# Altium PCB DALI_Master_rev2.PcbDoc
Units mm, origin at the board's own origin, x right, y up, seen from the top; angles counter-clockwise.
Board outline 90 x 50 mm, 2 copper layers (Top Layer, Bottom Layer); 97 components, 67 nets, 341 pads, 118 vias.
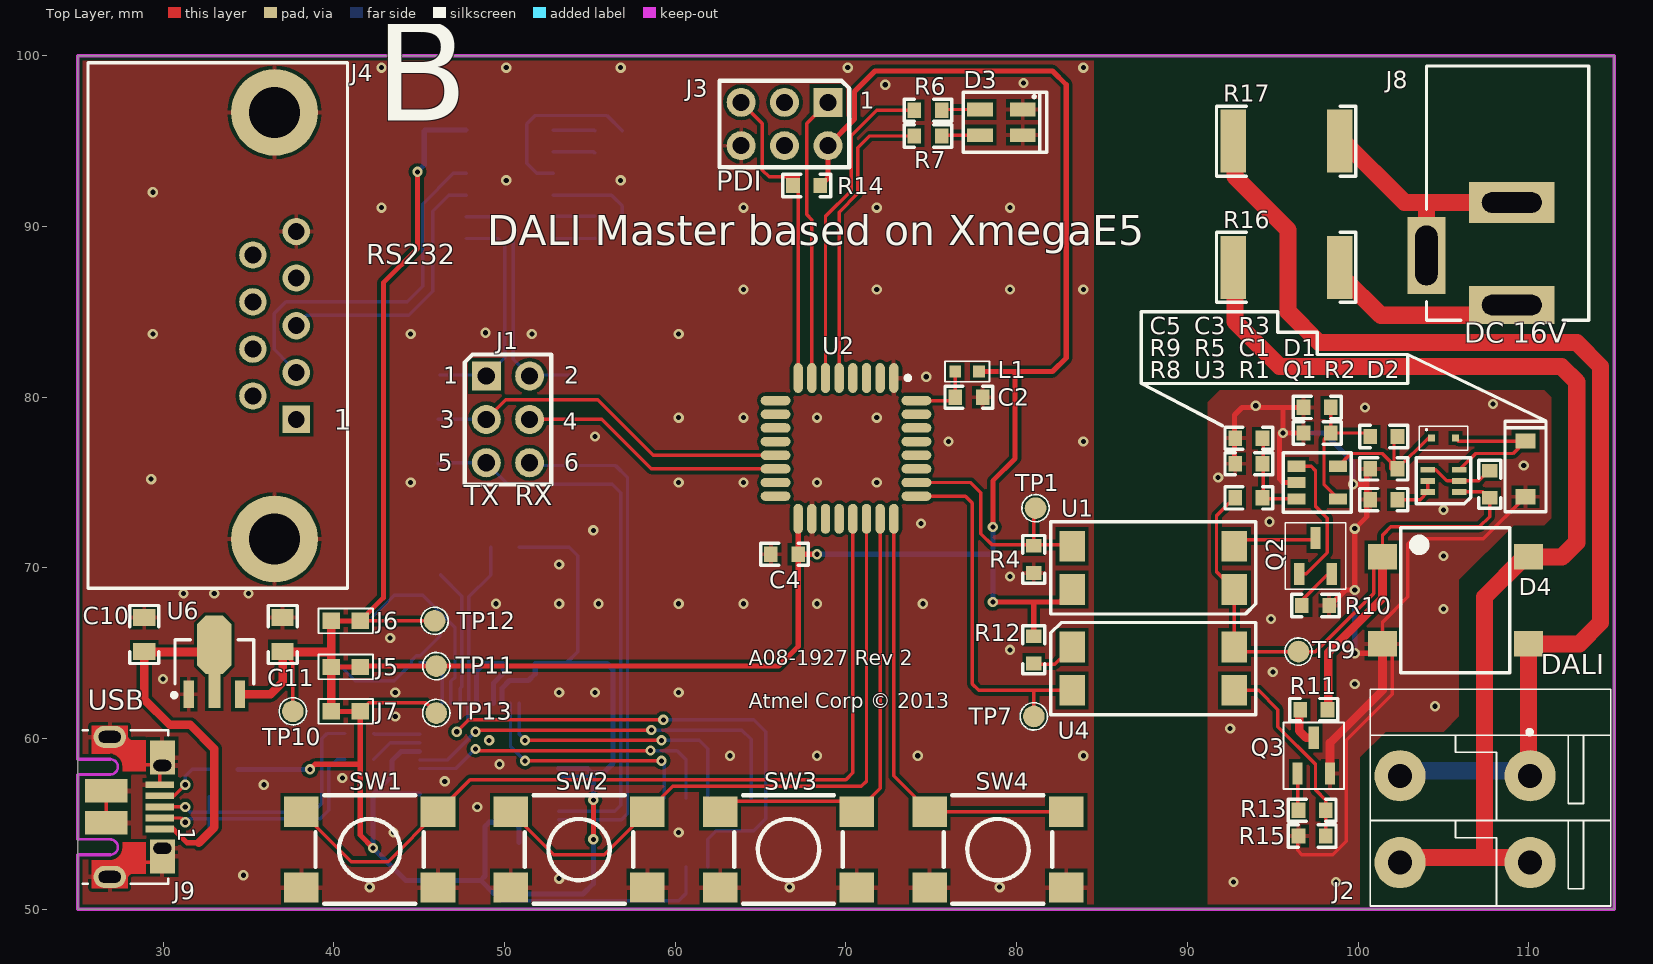
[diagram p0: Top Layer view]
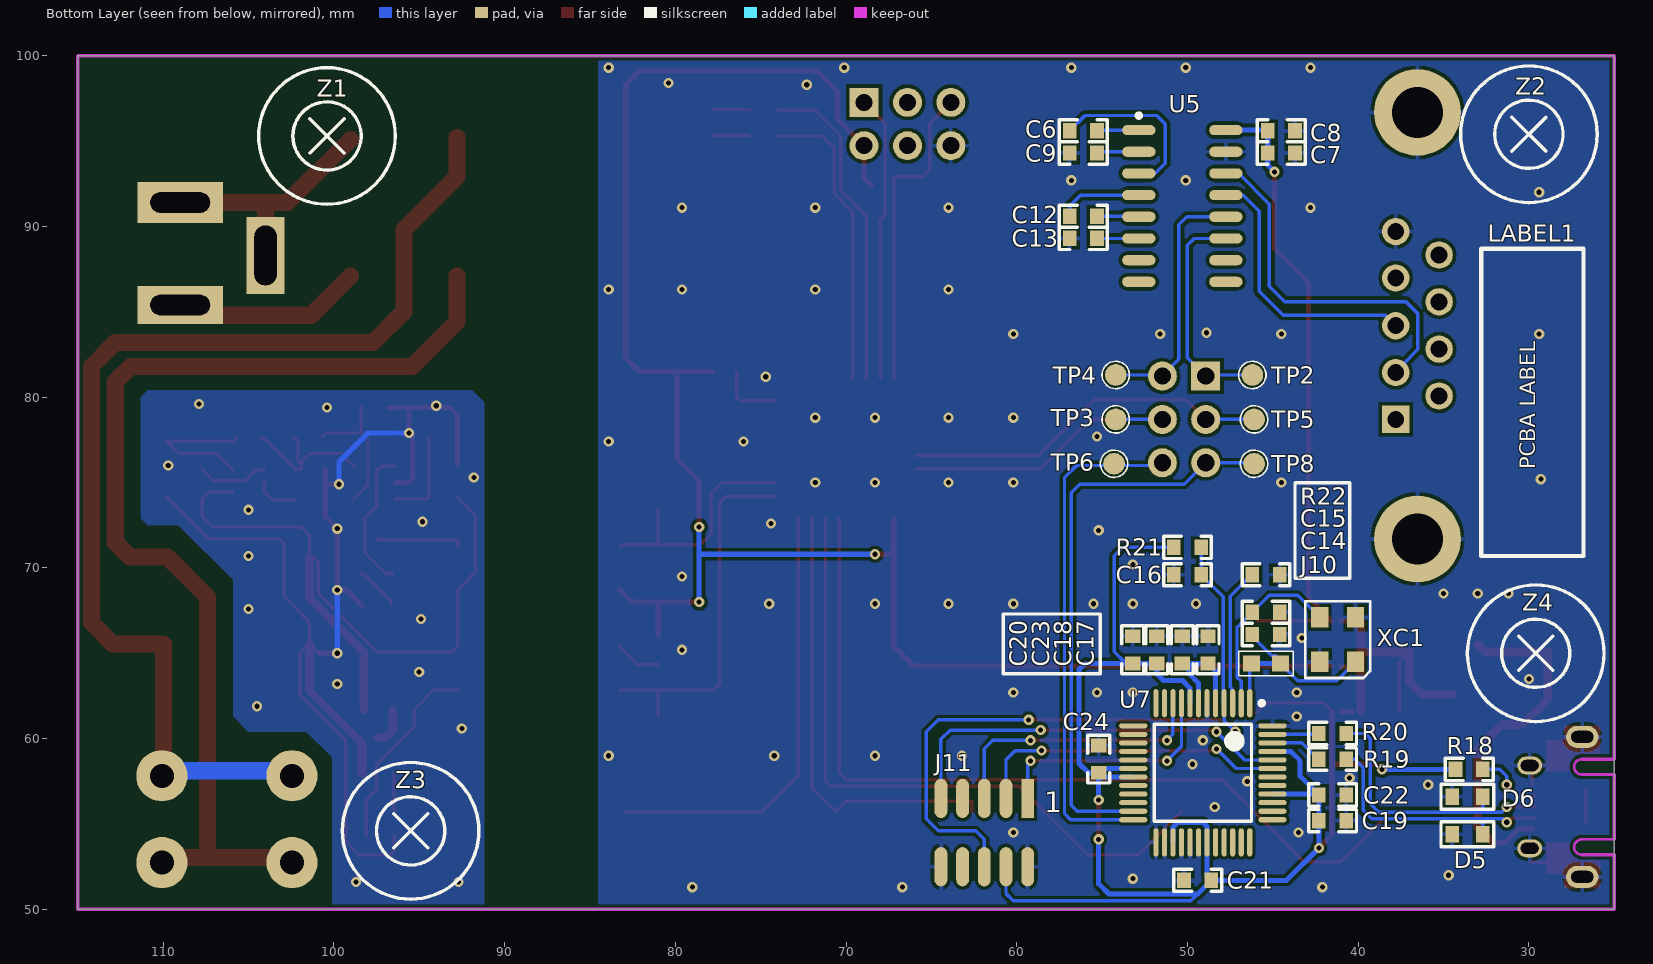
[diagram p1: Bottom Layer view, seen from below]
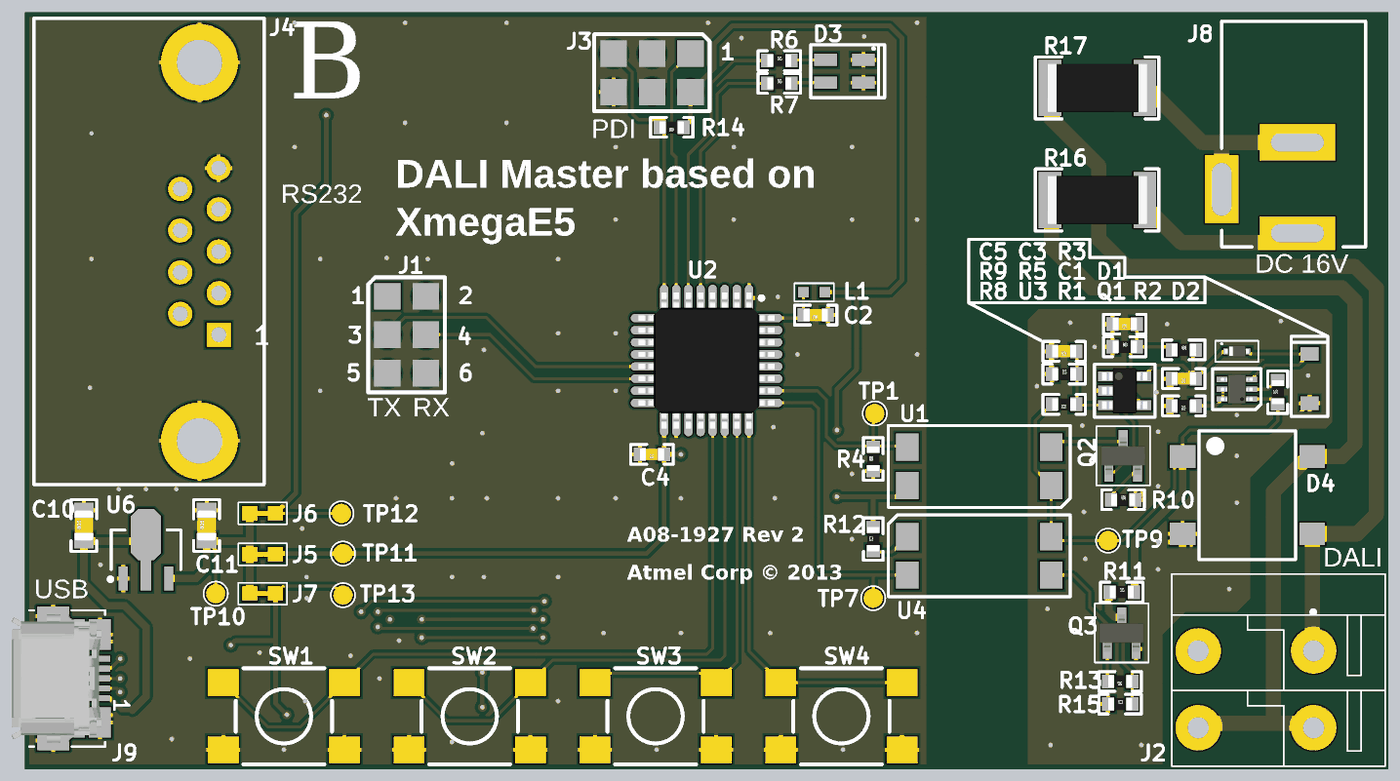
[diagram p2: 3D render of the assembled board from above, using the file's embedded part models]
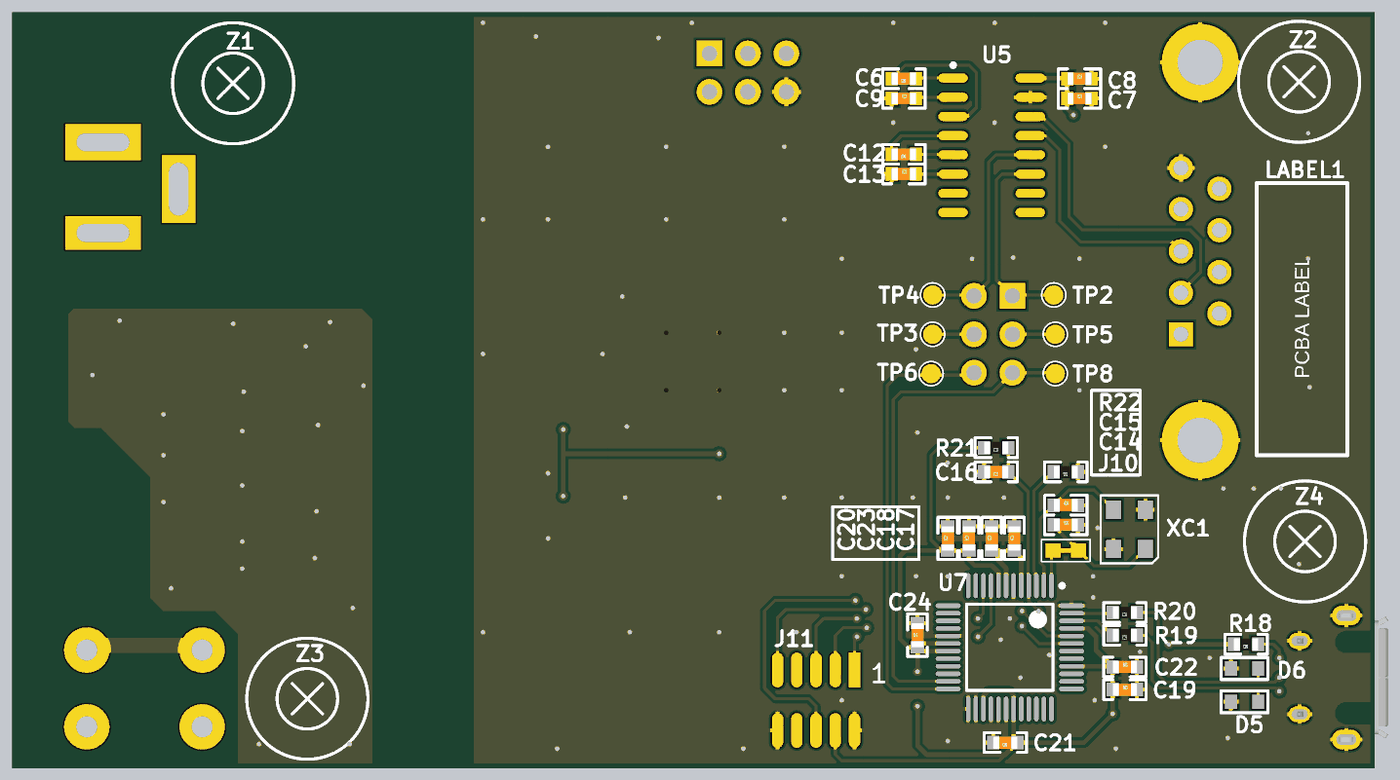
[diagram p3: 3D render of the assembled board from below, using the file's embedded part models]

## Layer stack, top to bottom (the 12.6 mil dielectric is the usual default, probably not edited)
Top Layer: signal copper 0.0356
Dielectric: dielectric 0.32, FR-4, Dk 4.8
Bottom Layer: signal copper 0.0356

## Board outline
25,50 25,100 115,100 115,50

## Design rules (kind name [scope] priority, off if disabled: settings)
Clearance [All] p1: gap=0.2
HoleSize [All] p1: absolutevalues=TRUE maxlimit=3.5 minlimit=0.025 maxpercent=80.000 minpercent=20.000
MinimumSolderMaskSliver [All] p1: minsoldermaskwidth=0.1
PolygonConnect [(InPadClass('All Pads'))] p1: connectstyle=Relief reliefconductorwidth=0.254 reliefentries=4 polygonreliefangle="90 Angle"
PolygonConnect PolygonConnect_1 [All] p2: connectstyle=Direct reliefconductorwidth=0.254 reliefentries=4 polygonreliefangle="90 Angle"
RoutingVias [All] p1: holewidth=0.3 width=0.6 viastyle="Through Hole" minholewidth=0.3 minwidth=0.6 maxholewidth=0.7 maxwidth=1
SilkscreenOverComponentPads [All] p1: minsilkscreentomaskgap=0.254
SolderMaskExpansion [All] p1: expansion=0.102
Width [All] p1: maxlimit=2 minlimit=0.2 preferedwidth=0.2
25 further rules are at their usual default settings.

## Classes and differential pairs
component class DALI_Master_Main_rev2: C1 C2 C3 C4 C5 D1 D2 D3 D4 J1 J2 J3 L1 LABEL1 Q1 Q2 Q3 R1 R2 R3 R4 R5 R6 R7 R8 R9 R10 R11 R12 R13 R14 R15 SW1 SW2 SW3 SW4 TP1 TP2 TP3 TP4 TP5 TP6 TP7 TP8 TP9 U1 U2 U3 U4 Z1 Z2 Z3 Z4
component class DALI_Master_Others_rev2: C6 C7 C8 C9 C10 C11 C12 C13 C14 C15 C16 C17 C18 C19 C20 C21 C22 C23 C24 D5 D6 J4 J5 J6 J7 J8 J9 J10 J11 R16 R17 R18 R19 R20 R21 R22 TP10 TP11 TP12 TP13 U5 U6 U7 U? XC1

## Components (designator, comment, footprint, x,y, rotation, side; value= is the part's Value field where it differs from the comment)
C1 "1735527 @ element14" AP1-00096#1 101.5,75.8 r180 top
C2 "1828890 @ element14" AP1-00096#1 77.2,80 r180 top
C3 "8819955 @ element14" AP1-00096#1 97.6,79.4 r180 top
C4 "1828890 @ element14" AP1-00096#1 66.4,70.8 r180 top
C5 "8819866 @ element14" AP1-00096#1 93.6,77.6 r180 top
C6 "1828890 @ element14" AP1-00096#2 56.1,95.6 r0 bottom
C7 "1735527 @ element14" AP1-00096#2 44.5,94.3 r180 bottom
C8 "1828890 @ element14" AP1-00096#2 44.5,95.6 r180 bottom
C9 "1828890 @ element14" AP1-00096#2 56.1,94.3 r180 bottom
C10 "1889282 @ element14" AP1-00097 28.9,66.1 r90 top
C11 "1889282 @ element14" AP1-00097 37,66.1 r90 top
C12 "1828890 @ element14" AP1-00096#2 56.1,90.6 r0 bottom
C13 "1828890 @ element14" AP1-00096#2 56.1,89.3 r180 bottom
C14 "1828907 @ element14" AP1-00096#1 45.4,66.1 r180 bottom
C15 "1828907 @ element14" AP1-00096#1 45.4,67.4 r180 bottom
C16 "1828890 @ element14" AP1-00096#1 50,69.6 r0 bottom
C17 "1735527 @ element14" AP1-00096#1 48.8,65.2 r90 bottom
C18 "1828890 @ element14" AP1-00096#1 50.3,65.2 r90 bottom
C19 "1735527 @ element14" AP1-00096#1 41.5,55.2 r180 bottom
C20 "1735527 @ element14" AP1-00096#1 53.2,65.2 r90 bottom
C21 "1828890 @ element14" AP1-00096#1 49.4,51.7 r0 bottom
C22 "1828890 @ element14" AP1-00096#1 41.5,56.7 r180 bottom
C23 "1828890 @ element14" AP1-00096#1 51.8,65.2 r90 bottom
C24 "1828890 @ element14" AP1-00096#1 55.2,58.8 r90 bottom
D1 "Farnell# 1615809" AP4-00036 105,77.6 r0 top
D2 "ZENER_SMD_12" AP4-00012 109.8,75.8 r90 top
D3 "LED2" AP4-00030 79.1,96.1 r0 top
D4 "DIODEBRIDGE" AP4-00009 105.7,68.1 r0 top
D5 "TransGuard" AP4-00024 33.6,54.4 r0 bottom
D6 "TransGuard" AP4-00024 33.6,56.6 r0 bottom
J1 "HEADER 2x3" AP8-00182 50.2,78.7 r270 top
J2 "Cable_connector_2Pin" AP8-00788 100.7,50.2 r270 top
J3 "HEADER 2x3" AP8-00182 66.4,96 r180 top
J4 "DSUB9" AP8-00516 37.8,78.7 r90 top
J5 "SMD-STRAP_CLOSED" AP9-00044#1 40.7,64.2 r180 top net-tie
J6 "SMD-STRAP_CLOSED" AP9-00044#2 40.7,66.9 r180 top net-tie
J7 "SMD-STRAP_CLOSED" AP9-00044#2 40.7,61.6 r180 top net-tie
J8 "Farnel #224959" AP8-00017 109,99 r270 top
J9 "USB_Micro" AP8-00610 29.8,56 r270 top
J10 "SMD-STRAP_CLOSED" AP9-00044#1 45.4,64.4 r180 bottom net-tie
J11 "2x5 Header" AP8-00514 61.9,54.5 r0 bottom
L1 "INDUCTOR" AP3-00005 77.1,81.5 r180 top
LABEL1 "Label PCBA" AP8-00317 26.8,70.7 r90 bottom
Q1 "PNP DUAL" AP5-00001 105,75.1 r180 top
Q2 "1081232 @ element14" AP5-00002 97.5,70.7 r90 top
Q3 "NPN BEC" AP5-00002 97.4,59 r90 top
R1 "9238743 @ element14" AP2-00066 101.5,74 r180 top
R2 "1799353 @ element14" AP2-00066 107.7,74.9 r90 top
R3 "9238840 @ element14" AP2-00066 101.5,77.7 r0 top
R4 "1799353 @ element14" AP2-00066 81,70.5 r90 top
R5 "9238840 @ element14" AP2-00066 97.6,77.9 r0 top
R6 "1255619 @element14" AP2-00066 74.8,96.8 r0 top
R7 "9238425 @element14" AP2-00066 74.8,95.3 r0 top
R8 "9238840 @ element14" AP2-00066 93.6,74.1 r180 top
R9 "R2" AP2-00066 93.6,76.1 r0 top
R10 "9238506 @element14" AP2-00066 97.5,67.8 r0 top
R11 "9238123 @ element14" AP2-00066 97.4,61.7 r0 top
R12 "1799335 @ element14" AP2-00066 81,65.2 r90 top
R13 "9238379 @element14" AP2-00066 97.3,55.8 r180 top
R14 "9238603 @ element14" AP2-00066 67.7,92.4 r180 top
R15 "1255619 @element14" AP2-00066 97.3,54.3 r0 top
R16 "1283115 @ element14" AP2-00068 95.8,87.6 r180 top
R17 "1283115 @ element14" AP2-00068 95.8,95 r180 top
R18 "9238689 @ element14" AP2-00066 33.5,58.2 r0 bottom
R19 "9238310 @ element14" AP2-00066 41.5,58.8 r0 bottom
R20 "9238310 @ element14" AP2-00066 41.5,60.3 r0 bottom
R21 "9238603 @ element14" AP2-00066 50,71.2 r0 bottom
R22 "9238603 @ element14" AP2-00066 45.4,69.6 r0 bottom
SW1 "B3S-1000P also can be used as MPN.Packaging difference only" AP8-00481 42.1,53.5 r90 top
SW2 "B3S-1000P also can be used as MPN.Packaging difference only" AP8-00481 54.367,53.5 r90 top
SW3 "B3S-1000P also can be used as MPN.Packaging difference only" AP8-00481 66.633,53.5 r90 top
SW4 "B3S-1000P also can be used as MPN.Packaging difference only" AP8-00481 78.9,53.5 r90 top
TP1 "INPUT" AP8-00499 81.1,73.5 r0 top
TP2 "" AP8-00499 46.2,81.3 r270 bottom
TP3 "" AP8-00499 54.2,78.7 r270 bottom
TP4 "" AP8-00499 54.2,81.3 r270 bottom
TP5 "" AP8-00499 46.1,78.7 r270 bottom
TP6 "" AP8-00499 54.3,76.1 r270 bottom
TP7 "OUTPUT" AP8-00499 81,61.3 r90 top
TP8 "" AP8-00499 46.1,76.1 r270 bottom
TP9 "" AP8-00499 96.5,65.1 r90 top
TP10 "+3V3" AP8-00499 37.6,61.6 r90 top
TP11 "" AP8-00499 46,64.25 r90 top
TP12 "" AP8-00499 45.9,66.9 r90 top
TP13 "" AP8-00499 46,61.5 r90 top
U1 "IS357" AP6-00142 88,70 r0 top
U2 "ATxmega32E5_TQFP" AP6-00061 70,77 r270 top
U3 "TLV3491" AP6-00087 97.6,75 r0 top
U4 "IS357" AP6-00142 88,64.1 r180 top
U5 "MAX3232" AP6-00122 50.3,91.2 r180 bottom
U6 "HT7533-2" AP5-00036 33,64.5 r90 top
U7 "ATSAM4LC2A" AP6-00004 49.1,58 r270 bottom locked
XC1 "1836841 @ element14" AP7-00041 41.2,65.8 r90 bottom
Z1 "Datasheet & Drawing in AP8-00414" AP8-00414 100.4,95.3 r180 bottom
Z2 "Datasheet & Drawing in AP8-00414" AP8-00414 30,95.4 r180 bottom
Z3 "Datasheet & Drawing in AP8-00414" AP8-00414 95.5,54.6 r180 bottom
Z4 "Datasheet & Drawing in AP8-00414" AP8-00414 29.6,65 r180 bottom

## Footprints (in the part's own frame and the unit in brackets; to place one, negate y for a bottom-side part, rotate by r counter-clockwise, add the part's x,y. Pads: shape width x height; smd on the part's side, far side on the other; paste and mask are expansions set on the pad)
AP1-00096#1 [mm] "0603 SMD capacitor footprint used by SHAPPS"
  rect 0.8x0.9 smd: 1(-0.8,0) 2(0.8,0)
  silkscreen extent -1.4,-0.65 1.4,0.65, body extent -0.8,-0.4 0.8,0.4, height 0.3
AP1-00096#2 [mm] "0603 SMD capacitor footprint used by SHAPPS"
  rect 0.8x0.9 smd paste-10: 1(-0.8,0) 2(0.8,0)
  silkscreen extent -1.4,-0.65 1.4,0.65, body extent -0.8,-0.4 0.8,0.4, height 0.3
AP1-00097 [mm] "0805 SMD capacitor footprint used by SHAPPS"
  rect 1x1.3 smd: 1(-1,0) 2(1,0)
  silkscreen extent -1.7,-0.85 1.7,0.85, body extent -1,-0.63 1,0.63, height 0.78
AP2-00066 [mm] "0603 SMD resistor footprint used by SHAPPS"
  rect 0.8x0.9 smd: 1(-0.8,0) 2(0.8,0)
  silkscreen extent -1.4,-0.65 1.4,0.65, body extent -0.8,-0.4 0.8,0.4, height 0.3
AP2-00068 [mm] "2512 SMD Resistor"
  rect 1.5x3.7 smd: 1(-3.125,0) 2(3.125,0)
  silkscreen extent -4.05,-2.05 4.1,2.05, body extent -3.3,-1.6 3.3,1.6, height 0.84
AP3-00005 [mm]
  rect 0.7x0.7 smd: 1(-0.7,0) 2(0.7,0)
  silkscreen extent -1.3,-0.6 1.3,0.6, body extent -0.83,-0.41 0.82,0.41, height 0.8
AP4-00009 [mm] "SOIC, 4-Leads, Body 8.5x6.5mm (max), Pitch 1.27mm, IPC Medium Density"
  rect 1.7x1.5 smd: 1(-4.275,2.55) 2(-4.275,-2.55) 3(4.275,-2.55) 4(4.275,2.55)
  silkscreen extent -3.2,-4.25 3.17,4.25, body extent -3.25,-4.25 3.25,4.25, height 3.3
AP4-00012 [mm]
  rect 0.9x1.2 smd: 1(1.63,0) 2(-1.63,0)
  silkscreen extent -2.5,-1.2 2.8,1.2, body extent -1.69,-0.9 1.71,0.9, height 1.21
AP4-00024 [mm]
  rect 0.8x0.95 smd: 1(-0.9,0) 2(0.9,0)
  silkscreen extent -1.55,-0.73 1.55,0.73, body extent -0.85,-0.4 0.85,0.4, height 0.4
AP4-00030 [mm]
  rect 1.5x0.8 smd: 1(1.25,0.75) 2(-1.25,0.75) 3(1.25,-0.75) 4(-1.25,-0.75)
  silkscreen extent -2.22,-1.75 2.65,1.75, body extent -1.5,-1.25 1.5,1.25, height 1.31
AP4-00036 [mm] "Molded Diode, 2-Leads, Body 1,2x0,8mm, IPC Medium Density"
  rect 0.4x0.4 smd: 1(-0.7,0) 2(0.7,0)
  silkscreen extent -1.43,-0.7 1.43,0.7, body extent -0.8,-0.4 0.8,0.4, height 0.7
AP5-00001 [mm]
  rect 0.85x0.35 smd: 1(-0.925,0.65) 2(-0.925,0) 3(-0.925,-0.65) 4(0.925,-0.65) 5(0.925,0) 6(0.925,0.65)
  silkscreen extent -1.6,-1.35 1.6,1.35, body extent -1.05,-1 1.05,1, height 0.95
AP5-00002 [mm] "SOT-23 Package"
  rect 1.3x0.6 smd: 1(-1.05,0.95) 2(-1.05,-0.95) 3(1.05,0)
  silkscreen extent -1.95,-1.78 1.95,1.78, body extent -1.25,-1.46 1.23,1.46, height 1
AP5-00036 [mm] "SOT89, 3-Leads, Body 4.5x2.4 mm, Pitch 1.5mm, Lead Span 4.1mm, IPC Low Density"
  rect 1.6x0.6 smd: 1(-1.9,1.5) 3(-1.9,-1.5)
  rect 2x0.7 smd: 2(-1.7,0)
  oct 3.4x2 smd: 2(1,0)
  silkscreen extent -2.07,-2.3 1.3,2.47, body extent -1.3,-2.3 1.3,2.3, height 1.6
AP6-00004 [mm] "TSQFP, 48-Leads, Body 9,0x9,0mm (max), Pitch 0,50mm, IPC Medium Density"
  oval 1.65x0.3 smd mask+0.05: 1(-4.075,2.75) 2(-4.075,2.25) 3(-4.075,1.75) 4(-4.075,1.25) 5(-4.075,0.75) 6(-4.075,0.25) 7(-4.075,-0.25) 8(-4.075,-0.75) 9(-4.075,-1.25) 10(-4.075,-1.75) 11(-4.075,-2.25) 12(-4.075,-2.75) 25(4.075,-2.75) 26(4.075,-2.25) 27(4.075,-1.75) 28(4.075,-1.25) 29(4.075,-0.75) 30(4.075,-0.25) 31(4.075,0.25) 32(4.075,0.75) 33(4.075,1.25) 34(4.075,1.75) 35(4.075,2.25) 36(4.075,2.75)
  oval 0.3x1.65 smd mask+0.05: 13(-2.75,-4.075) 14(-2.25,-4.075) 15(-1.75,-4.075) 16(-1.25,-4.075) 17(-0.75,-4.075) 18(-0.25,-4.075) 19(0.25,-4.075) 20(0.75,-4.075) 21(1.25,-4.075) 22(1.75,-4.075) 23(2.25,-4.075) 24(2.75,-4.075) 37(2.75,4.075) 38(2.25,4.075) 39(1.75,4.075) 40(1.25,4.075) 41(0.75,4.075) 42(0.25,4.075) 43(-0.25,4.075) 44(-0.75,4.075) 45(-1.25,4.075) 46(-1.75,4.075) 47(-2.25,4.075) 48(-2.75,4.075)
  silkscreen extent -4.2,-2.85 2.85,3.57, body extent -3.5,-3.5 3.5,3.5, height 1.2
AP6-00061 [mm] "TQFP, 32-Leads, Body 9.3x9.3mm (max), Pitch 0.80mm, IPC Medium Density"
  oval 1.75x0.55 smd: 1(-4.125,2.8) 2(-4.125,2) 3(-4.125,1.2) 4(-4.125,0.4) 5(-4.125,-0.4) 6(-4.125,-1.2) 7(-4.125,-2) 8(-4.125,-2.8) 17(4.125,-2.8) 18(4.125,-2) 19(4.125,-1.2) 20(4.125,-0.4) 21(4.125,0.4) 22(4.125,1.2) 23(4.125,2) 24(4.125,2.8)
  oval 0.55x1.75 smd: 9(-2.8,-4.125) 10(-2,-4.125) 11(-1.2,-4.125) 12(-0.4,-4.125) 13(0.4,-4.125) 14(1.2,-4.125) 15(2,-4.125) 16(2.8,-4.125) 25(2.8,4.125) 26(2,4.125) 27(1.2,4.125) 28(0.4,4.125) 29(-0.4,4.125) 30(-1.2,4.125) 31(-2,4.125) 32(-2.8,4.125)
  silkscreen extent -4.25,3.5 -4,3.75, body extent -4.5,-4.5 4.5,4.5, height 1.44
AP6-00087 [mm]
  rect 1.05x0.65 smd: 1(-1.225,0.953) 2(-1.225,0) 3(-1.225,-0.953) 4(1.225,-0.953) 5(1.225,0.953)
  silkscreen extent -2,-1.75 2,1.75, body extent -1.5,-1.5 1.5,1.5, height 1.3
AP6-00122 [mm]
  oval 1.95x0.6 smd paste-10: 1(-2.55,4.445) 2(-2.55,3.175) 3(-2.55,1.905) 4(-2.55,0.635) 5(-2.55,-0.635) 6(-2.55,-1.905) 7(-2.55,-3.175) 8(-2.55,-4.445) 9(2.55,-4.445) 10(2.55,-3.175) 11(2.55,-1.905) 12(2.55,-0.635) 13(2.55,0.635) 14(2.55,1.905) 15(2.55,3.175) 16(2.55,4.445)
  silkscreen extent -2.68,5.17 -2.43,5.42, body extent -2,-5 2,5, height 1.75
AP6-00142 [mm]
  rect 1.5x1.8 smd: 1(4.75,-1.27) 2(4.75,1.27) 3(-4.75,1.27) 4(-4.75,-1.27)
  silkscreen extent -6,-2.7 6,2.7, body extent -3.4,-2.4 3.4,2.4, height 4
AP7-00041 [mm] "FOX FQ5032B"
  rect 1.2x1 smd: 1(-1.3,-1.05) 2(1.3,-1.05) 3(1.3,1.05) 4(-1.3,1.05)
  silkscreen extent -2.25,-1.9 2.25,1.9, body extent -1.6,-1.25 1.6,1.25, height 1.1
AP8-00017 [mm]
  rect 2.4x5 hole 1.2 slot 3.5 at 90 deg: 1(7.6,0)
  rect 4.5x2.2 hole 1.3 slot 3.5 at 0 deg: 2(10.7,-5)
  rect 2.2x5 hole 1.2 slot 3.5 at 90 deg: 3(13.6,0)
  silkscreen extent -0.4,-5 14.5,4.5, body extent 0,-5 14,4.5, height 10
AP8-00182 [mm] "Pin-in-Paste, Throughhole pin-header (2x3 array). Pitch 2.54 mm"
  rect 1.7x1.7 / inner round 1.7 / far side rect 1.7x1.7 hole 1: 1(-2.54,-1.27)
  rect 1.75x1.75 on Top Paste paste-10: 1(-2.54,-1.27) 2(-2.54,1.27) 3(0,-1.27) 4(0,1.27) 5(2.54,-1.27) 6(2.54,1.27)
  round 1.7 hole 1: 2(-2.54,1.27) 3(0,-1.27) 4(0,1.27) 5(2.54,-1.27) 6(2.54,1.27)
  silkscreen extent -3.8,-2.54 3.81,2.54, body extent -3.81,-2.54 3.81,2.54, height 8
AP8-00317 [mm] "Placement area for 18x6mm sticker"
  silkscreen extent 0,0 18,6
AP8-00414 [mm] "RubberFoot 8.0x2.5mm"
  silkscreen extent -4,-4 4,4
AP8-00481 [mil]
  rect 70x80 smd paste-393.7: 1(-87.5,157.5) 2(-87.5,-157.5) 3(87.5,157.5) 4(87.5,-157.5)
  silkscreen extent -125,-125 125,125, body extent -120,-130 120,130, height 169
AP8-00499 [mm] "Testpad 50mil"
  round 1.27 smd paste-0.635: 1(0,0)
  silkscreen extent -0.8,-0.8 0.8,0.8
AP8-00514 [mm] "JP_2.5_1.27_SMD"
  rect 0.75x2.3 smd paste-10: 1(-2.54,-2)
  oval 0.75x2.3 smd paste-10: 2(-2.54,2) 3(-1.27,-2) 4(-1.27,2) 5(0,-2) 6(0,2) 7(1.27,-2) 8(1.27,2) 9(2.54,-2) 10(2.54,2)
  body extent -3.17,-2.73 3.17,2.73, height 4.78
AP8-00516 [mil] "DSUB9, right angle, THM"
  rect 63x63 hole 39: 1(0,0)
  round 63 hole 39: 2(108,0) 3(216,0) 4(326,0) 5(433,0) 6(54,100) 7(162,100) 8(271,100) 9(379,100)
  round 200 hole 118: 10(-276,50) 11(708,50)
  silkscreen extent -390,-118 823,480
AP8-00610 [mm]
  rect 0.4x1.65 smd: 1(1.3,0) 2(0.65,0) 3(0,0) 4(-0.65,0) 5(-1.3,0)
  oval 1.3x1.9 hole 0.7 slot 1.3 at 90 deg: 6(-4.1,-2.925) 7(4.1,-2.925)
  rect 1.375x2.5 smd: 8(-0.937,-3.125) 9(0.937,-3.125)
  rect 2x1.46 smd: 10(-2.9,0.155) 11(2.9,0.155)
  oval 1.05x1.45 hole 0.65 slot 1.05 at 90 deg: 10(-2.425,0.155) 11(2.425,0.155)
  Top Layer region: -2.075,-2.175 -2.075,-2.175 -2.375,-2.175 -2.375,-2.175 -2.399,-2.175 -2.422,-2.176 -2.446,-2.178 -2.469,-2.181 -2.492,-2.184 -2.516,-2.188 -2.539,-2.193 -2.562,-2.198 -2.584,-2.205 -2.607,-2.212 -2.629,-2.219 -2.651,-2.228 -2.673,-2.237 -2.694,-2.246 -2.716,-2.257 -2.736,-2.268 -2.757,-2.279 -2.777,-2.292 -2.797,-2.305 -2.816,-2.318 -2.835,-2.332 -2.853,-2.347 -2.871,-2.362 -2.888,-2.378 -2.905,-2.395 -2.922,-2.412 -2.938,-2.429 -2.953,-2.447 -2.968,-2.465 -2.982,-2.484 -2.995,-2.503 -3.008,-2.523 -3.021,-2.543 -3.032,-2.564 -3.043,-2.584 -3.054,-2.606 -3.063,-2.627 -3.072,-2.649 -3.081,-2.671 -3.088,-2.693 -3.095,-2.716 -3.102,-2.738 -3.107,-2.761 -3.112,-2.784 -3.116,-2.808 -3.119,-2.831 -3.122,-2.854 -3.124,-2.878 -3.125,-2.901 -3.125,-2.924 -3.125,-2.925 -3.125,-3.975 -4.75,-3.975 -4.75,-1.875 -4.2,-1.875 -4.185,-1.875 -4.171,-1.874 -4.156,-1.872 -4.141,-1.869 -4.127,-1.866 -4.113,-1.862 -4.099,-1.858 -4.085,-1.852 -4.072,-1.846 -4.059,-1.84 -4.046,-1.832 -4.033,-1.825 -4.021,-1.816 -4.01,-1.807 -3.998,-1.797 -3.988,-1.787 -3.978,-1.777 -3.968,-1.765 -3.959,-1.754 -3.95,-1.742 -3.943,-1.729 -3.935,-1.716 -3.929,-1.703 -3.923,-1.69 -3.917,-1.676 -3.913,-1.662 -3.909,-1.648 -3.906,-1.634 -3.903,-1.619 -3.901,-1.604 -3.9,-1.59 -3.9,-1.575 -3.9,-0.825 -2.075,-0.825
  Top Layer region: 2.075,-2.175 2.075,-2.175 2.375,-2.175 2.375,-2.175 2.399,-2.175 2.422,-2.176 2.446,-2.178 2.469,-2.181 2.492,-2.184 2.516,-2.188 2.539,-2.193 2.562,-2.198 2.584,-2.205 2.607,-2.212 2.629,-2.219 2.651,-2.228 2.673,-2.237 2.694,-2.246 2.716,-2.257 2.736,-2.268 2.757,-2.279 2.777,-2.292 2.797,-2.305 2.816,-2.318 2.835,-2.332 2.853,-2.347 2.871,-2.362 2.888,-2.378 2.905,-2.395 2.922,-2.412 2.938,-2.429 2.953,-2.447 2.968,-2.465 2.982,-2.484 2.995,-2.503 3.008,-2.523 3.021,-2.543 3.032,-2.564 3.043,-2.584 3.054,-2.606 3.063,-2.627 3.072,-2.649 3.081,-2.671 3.088,-2.693 3.095,-2.716 3.102,-2.738 3.107,-2.761 3.112,-2.784 3.116,-2.808 3.119,-2.831 3.122,-2.854 3.124,-2.878 3.125,-2.901 3.125,-2.924 3.125,-2.925 3.125,-3.975 4.75,-3.975 4.75,-1.875 4.2,-1.875 4.185,-1.875 4.171,-1.874 4.156,-1.872 4.141,-1.869 4.127,-1.866 4.113,-1.862 4.099,-1.858 4.085,-1.852 4.072,-1.846 4.059,-1.84 4.046,-1.832 4.033,-1.825 4.021,-1.816 4.01,-1.807 3.998,-1.797 3.988,-1.787 3.978,-1.777 3.968,-1.765 3.959,-1.754 3.95,-1.742 3.943,-1.729 3.935,-1.716 3.929,-1.703 3.923,-1.69 3.917,-1.676 3.913,-1.662 3.909,-1.648 3.906,-1.634 3.903,-1.619 3.901,-1.604 3.9,-1.59 3.9,-1.575 3.9,-0.825 2.075,-0.825
  silkscreen extent -4.5,-4.5 4.5,0.5, body extent -4.25,-5.67 4.25,0.32, height 2.73
AP8-00788 [mm] "Cable connector, 2Pin, through-hole"
  round 3 hole 1.4: 1(-7.62,9.37) 1(-7.62,1.75) 2(-2.54,9.37) 2(-2.54,1.75)
  silkscreen extent -12.7,0 0,14.1, body extent -12.7,0 0,14.1, height 1.6
AP9-00044#1 [mm]
  rect 1x0.95 smd paste-1: 1(-0.85,0) 2(0.85,0)
  Top Layer region: -0.45,-0.15 0.45,-0.15 0.45,0.15 -0.45,0.15
  silkscreen extent -1.6,-0.72 1.6,0.72, body extent -0.8,-0.4 0.8,0.4, height 0.3
AP9-00044#2 [mm]
  rect 1x0.95 smd paste-10: 1(-0.85,0) 2(0.85,0)
  Top Layer region: -0.45,-0.15 0.45,-0.15 0.45,0.15 -0.45,0.15
  silkscreen extent -1.6,-0.72 1.6,0.72, body extent -0.8,-0.4 0.8,0.4, height 0.3

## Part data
C1 C7 C17 C19 C20: library part A01-0596, "Ceramic capacitor, SMD 0603, X5R, 6.3V, ?0%"
C2 C4 C6 C8 C9 C12 C13 C16 C18 C21 C22 C23 C24: library part A01-0597, "Ceramic capacitor, SMD 0603, X7R, 16V, ?0%"
C3: library part A01-0598, "Ceramic capacitor, SMD 0603, X7R, 50V, ?0%"
C5: library part A01-0599, "Ceramic capacitor, SMD 0603, C0G, 50V, ?%"
C10 C11: library part A01-0601, "Ceramic capacitor, SMD 0805, X6S, 16V, ?0%"
C14 C15: library part A01-0600, "Ceramic capacitor, SMD 0603, C0G, 50V, ?%"
D1: library part A04-0049, "Schottky diode, If:200mA, Vf:0.35V, Vrrm:30V, SOD-523"
D2: library part A04-0093, "2.7V 500mW SOD-123"
D3: library part A10-0027, "LED, 2 colour (RED/GREEN), transparent clear lens, SMD"
D4: library part A04-0007, "SMD bridge rectifier, 1A, Vrrm=1k, Vrms=700, Vdc=1k"
D5 D6: library part A04-0018, "ESD Suppressor"
J1 J3: library part A08-0006, "2x3 pin header, 2.54 mm pitch, Pin-in-Paste THM"
J2: library part A08-1925, "Cable connector, 2Pin, through-hole"
J4: library part A08-1327, "DSUB9, right angle, THM (de2063)"
J5 J6 J7 J10: library part A09-0783, "Default closed SMD strap, 0603 size"
J8: library part A08-0640, "Through hole DC jack 2.1mm"
J9: library part A08-1472, "Micro USB B Connector"
J11: library part A08-1323, "2x5 Header, SMD, Pitch1.27mm, Height4.68mm (de13733)"
L1: library part A03-0036, "SMD RF inductor 0603. Z=1500Ohm (@100MHz), Max R(dc)=0.50Ohm, Max current=500mA"
LABEL1: library part A09-0611, "PCBA identification label PP Top White Gloss"
Q1: library part A05-0037, "General purpose SMD small signal BJT Dual transistor, 2xPNP. Body Sot363"
Q2: library part A05-0126, "General purpose SMD small signal BJT transistor. Polarity:NPN, Body:SOT23, P(tot)=0.25W, V(ceo)=45V, I(c)=0.1A, h(fe)=200/450, f(t)=100MHz"
Q3: library part A05-0125, "General purpose SMD small signal BJT transistor. Polarity:NPN, Body:SOT23,"
R1: library part A02-0815, "SMD 0603, 1/10W, 1%"
R2 R4: library part A02-0814, "SMD 0603, 1/10W, 1%"
R3 R5 R8: library part A02-0816, "SMD 0603, 1/10W, 1%"
R6 R15: library part A02-0819, "SMD 0603, 1/10W, 1%"
R7: library part A02-0822, "SMD 0603, 1/10W, 1%"
R9: library part A02-0817, "SMD 0603, 1/10W, 1%"
R10: library part A02-0818, "SMD 0603, 1/10W, 1%"
R11: library part A02-0825, "SMD 0603, 1/10W, 1%"
R12: library part A02-0826, "SMD 0603, 1/10W, 1%"
R13: library part A02-0820, "SMD 0603, 1/10W, 1%"
R14 R21 R22: library part A02-0821, "SMD 0603, 1/10W, 1%"
R16 R17: library part A02-0831, "SMD 2512, 1W, 1%"
R18: library part A02-0827, "SMD 0603, 1/10W, 1%"
R19 R20: library part A02-0823, "SMD 0603, 1/10W, 1%"
SW1 SW2 SW3 SW4: library part A08-1855, "Sealed Surface-mounting Tactile Switch"
TP1 TP2 TP3 TP4 TP5 TP6 TP7 TP8 TP9 TP10 TP11 TP12 TP13: library part A08-1274, "Single SMD testpad"
U1 U4: library part A10-0103, "Optocoupler, High Reliability, 5300 VRMS"
U2: library part A06-0854, "AVR 8-bit RISC MCU TQFP32"
U3: library part A06-0912, "1.8V, Nanopower, PUSH-PULL OUTPUT COMPARATOR,sot23-5"
U5: library part A06-0733, "RS-232 TRANSCEIVER, SO16, SMD (de21819)"
U6: library part A06-1050, "100mA Low Power LDO"
U7: library part A06-1043, "32-bit ARM MCU, SAM4L Series"
XC1: library part A07-0096, "12MHz uXtal, 3.2 x 2.5 mm SMD, CL=18pF, 30PPM"
Z1 Z2 Z3 Z4: library part A08-0977, "adhesive PU Rubber foot, lucent, diam. 9.5mm height 3.8mm (de15815)"

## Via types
v1: diameter 0.6, hole 0.3, Top Layer to Bottom Layer, 118 vias

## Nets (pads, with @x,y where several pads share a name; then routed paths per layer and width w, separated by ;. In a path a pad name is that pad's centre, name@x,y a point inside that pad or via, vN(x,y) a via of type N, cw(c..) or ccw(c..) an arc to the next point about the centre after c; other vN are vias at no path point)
DALI_BUS_1: D4.4 J2.2 R16.2 | length 63.2
  Top Layer w1: R16.2@92.775,87.1 92.775,84.425 95.4,81.8 111.9,81.8 112.8,80.9 112.8,71.5 111.95,70.65 D4.4 109.75,70.65 107.4,68.3 107.4,53.04 ; J2.2@102.05,53.04 J2.2@109.67,53.04
DALI_BUS_2: D4.3 J2.1 R17.2 | length 65.6
  Top Layer w1: R17.2@92.775,95.2 92.775,92.925 95.9,89.8 95.9,85 97.7,83.2 112.8,83.2 114.2,81.8 114.2,66.8 112.95,65.55 D4.3 J2.1@109.975,58.425
  Bottom Layer w1: J2.1@102.05,58.12 J2.1@109.67,58.12
DALI_INPUT: R4.2 TP1.1 U1.3 U2.26 | length 14.3
  Top Layer w0.2: U2.26 77.3,75 77.9,74.4 77.9,72 78.55,71.35 R4.2@81,71.35 ; TP1.1 81,73.4 R4.2@81,71.35 ; U1.3 83.17,71.35 R4.2@81,71.35
DALI_OUTPUT: TP7.1 U2.25 U4.2 | length 21.6
  Top Layer w0.2: U2.25 77,74.2 77.4,73.8 77.4,63.2 77.77,62.83 81,62.83 ; TP7.1 81,62.83 ; U4.2 81,62.83
DM_3V3: C4.1 J3.2@68.94,94.73 J5.1 L1.1 R12.2 R14.1 TP11.1 U1.4 U2.17 | length 106.9
  Top Layer w0.3: J5.1@41.6,64.25 TP11.1 66.05,64.25 67.2,65.4 C4.1 ; U2.17 C4.1 ; v1(68.3,70.8) C4.1 ; R14.1 68.94,92.84 68.94,94.73 70.5,96.29 70.5,97.9 71.7,99.1 82.1,99.1 82.9,98.3 82.9,82.3 82.1,81.5 L1.1 ; v1(78.6,68) 81,68 ; v1(78.6,72.4) 78.6,75.1 79.9,76.4 79.9,81.5 ; R12.2@81,66.05 81,68 ; U1.4 82.52,68 81,68
  Bottom Layer w0.3: v1(68.3,70.8) 78.6,70.8 ; v1(78.6,68) 78.6,70.8 ; v1(78.6,72.4) 78.6,70.8
GND: C2.1 C4.2 C7.2 C8.2 C9.1 C10.2 C11.2 C13.1 C14.2 C15.2 C16.2 C17.2 C18.2 C19.2 C20.2 C21.2 C22.2 C23.2 C24.2 D3.1 D3.3 D5.2 D6.2 J3.6@63.86,94.73 J4.5 J4.10 J4.11 J9.5 J9.6 J9.7 J9.8 J9.9 J9.10 J9.11 J11.2 J11.10 R4.1 R22.1 SW1.1 SW1.2 SW2.1 SW2.2 SW3.1 SW3.2 SW4.1 SW4.2 U2.1 U2.18 U5.15 U6.1 U7.6 U7.17 U7.25 U7.26 U7.28 U7.29 U7.30 U7.48 XC1.2 XC1.4 | length 8.5
  Top Layer w0.2: J9.9 J9.8 ; J9.6 28.5,58.475 ; 28.213,58.475 28.5,58.475 ; 28.987,52.75 J9.11@29.955,52.75 ; J9.5 J9.10@29.8,58.745 ; J9.10@29.955,58.9 J9.10@29.8,58.745 ; 28.5,58.475 29.53,58.475 J9.10@29.8,58.745
  other v1: 42.1,51.3 66.7,51.3 79,51.3 53.2,51.8 34.7,52 43.5,54.5 60.2,54.5 48.4,56 35.9,57.3 46.5,57.5 40.5,57.7 49.7,58.5 63.2,59 68.3,59 74.2,59 83.9,59 49.1,59.9 43.6,61.3 43.6,62.7 53.2,62.7 55.3,62.7 60.2,62.7 30,63.5 79.6,65.2 43.3,65.9 49.5,67.9 53.2,67.9 55.5,67.9 60.2,67.9 64,67.9 68.3,67.9 74.5,67.9 31.2,68.5 33,68.5 35,68.5 79.6,69.5 53.2,70.2 55.2,72.2 74.4,72.6 44.5,75 60.2,75 64,75 68.3,75 71.8,75 29.3,75.2 76,77.4 83.9,77.4 55.3,77.7 60.2,78.8 64,78.8 68.3,78.8 71.8,78.8 74.7,81.2 29.4,83.7 44.5,83.7 51.6,83.7 60.2,83.7 48.885,83.773 64,86.3 71.8,86.3 79.6,86.3 83.9,86.3 42.8,91.1 64,91.1 71.8,91.1 79.6,91.1 29.4,92 50.1,92.7 56.8,92.7 72.3,98.3 80.4,98.4 42.8,99.3 50.1,99.3 56.8,99.3 70.1,99.3 83.9,99.3
GND_DALI: C1.2 C3.2 C5.2 D2.2 D4.2 Q3.2 R1.2 R5.1 R9.1 R10.2 R15.1 U3.2 | length 75.6
  Top Layer w0.2: R15.1@96.45,54.3 96.45,53.45 96.7,53.2 98.5,53.2 99.3,54 99.3,59.9 102,62.6 102,64.975 D4.2 ; D4.2@100.875,65 D4.2 ; D2.2 107.33,71.7 103.2,71.7 102.9,71.4 102.9,68.3 101.425,66.825 D4.2
  Top Layer w0.3: R9.1@92.75,76.1 92.75,78.95 93.2,79.4 C3.2 ; v1@95.4,77.9 95.4,75.2 95.6,75 U3.2 ; 95.6,79.4 v1(95.6,77.9) R5.1@96.75,77.9 ; R10.2@98.35,67.8 99.25,68.7 v1(99.8,68.7) v1(99.8,72.3) 100.502,73.002 100.502,74.9 ; v1(99.7,74.9) 100.502,74.9 ; v1(99.8,65) D4.2@100.875,65 ; C1.2@100.502,75.8 100.502,74.9
  Top Layer w0.5: Q3.2 98.35,59.75 101.425,62.825 D4.2
  Bottom Layer w0.3: v1(95.6,77.9) 98,77.9 99.7,76.2 v1(99.7,74.9) ; v1(99.8,65) v1(99.8,68.7)
  other v1: 92.7,51.6 98.7,51.6 92.5,60.6 104.5,61.9 99.8,63.2 95,63.9 94.9,67 105,67.6 105,70.7 94.8,72.7 105,73.4 91.8,75.3 109.7,76 100.4,79.4 94,79.5 107.9,79.6
JTAG_TCK: J11.1 U7.9 | length 14
  Top Layer w0.2: v1(51.2,58.7) v1(59.2,58.7)
  Bottom Layer w0.2: U7.9 50.35,59.55 v1(51.2,58.7) ; v1(59.2,58.7) 59.36,58.54 J11.1
JTAG_TDI: J11.9 U7.44 | length 23.8
  Top Layer w0.2: v1(48.3,60.4) 48.4,60.5 55.7,60.5 v1(58.6,60.5)
  Bottom Layer w0.2: U7.44 46.65,58.75 v1(48.3,60.4) ; v1(58.6,60.5) 63.9,60.5 64.44,59.96 J11.9
JTAG_TDO: J11.3 U7.43 | length 18.6
  Top Layer w0.2: v1(48.3,59.4) 48.4,59.3 v1(58.552,59.3)
  Bottom Layer w0.2: U7.43 47.15,58.25 v1(48.3,59.4) ; v1(58.552,59.3) 60.1,59.3 60.63,58.77 J11.3
JTAG_TMS: J11.5 U7.10 | length 16.1
  Top Layer w0.2: v1(51.2,59.9) v1(59.2,59.9)
  Bottom Layer w0.2: U7.10 50.85,60.25 v1(51.2,59.9) ; v1(59.2,59.9) 61.4,59.9 61.9,59.4 J11.5
LED1: R6.1 U2.6 | length 19.1
  Top Layer w0.2: U2.6 68.8,90.6 70.3,92.1 70.3,95.3 71.8,96.8 R6.1
LED2: R7.1 U2.5 | length 17.5
  Top Layer w0.2: U2.5 69.6,90.834 70.7,91.934 70.7,94.6 71.4,95.3 R7.1
MCU_3V3: C2.2 L1.2 U2.32 | length 3.9
  Top Layer w0.2: U2.32 76.2,79.8 C2.2 L1.2
NetC1_1: C1.1 D1.1 R3.2 U3.5 | length 9
  Top Layer w0.2: U3.5 99.572,76.7 101.4,76.7 101.899,76.201 101.899,75.8 C1.1 104.1,77.6 D1.1 ; 101.899,76.001 102.1,76.203 102.1,77.45 R3.2@102.35,77.7
NetC3_1: C3.1 R3.1 R5.2 U3.4 | length 8.1
  Top Layer w0.2: C3.1 98.4,77.95 98,77.55 98,74.872 U3.4 ; R5.2@98.45,77.9 100.45,77.9 R3.1@100.65,77.7
NetC5_1: C5.1 R8.1 R9.2 U3.3 | length 5.5
  Top Layer w0.2: C5.1 94.45,77.55 94.45,74.1 94.503,74.047 U3.3
NetC6_1: C6.1 U5.1 | length 2.5
  Bottom Layer w0.2: U5.1 55.255,95.645 C6.1
NetC6_2: C6.2 U5.3 | length 10.3
  Bottom Layer w0.2: U5.3 51.895,93.105 51.3,93.7 51.3,96 51.8,96.5 56,96.5 C6.2
NetC9_2: C9.2 U5.2 | length 2.5
  Bottom Layer w0.2: U5.2 55.225,94.375 C9.2
NetC12_1: C12.1 U5.5 | length 2.5
  Bottom Layer w0.2: U5.5 52.885,90.6 C12.1
NetC12_2: C12.2 U5.4 | length 4.9
  Bottom Layer w0.2: U5.4 56.265,91.835 56.9,91.2 C12.2
NetC13_2: C13.2 U5.6 | length 2.5
  Bottom Layer w0.2: U5.6 55.295,89.295 C13.2
NetC14_1: C14.1 J10.2 XC1.1 | length 7.8
  Bottom Layer w0.2: XC1.1 41.25,63.4 43.55,63.4 J10.2 44.55,64.574 44.826,64.85 45.05,64.85 46.2,66 C14.1
NetC15_1: C15.1 U7.2 XC1.3 | length 10.7
  Bottom Layer w0.2: XC1.3 43.55,68.4 45.2,68.4 C15.1 47.1,66.5 47.1,63.6 46.85,63.35 U7.2
NetD1_2: D1.2 D2.1 Q1.3 | length 8.7
  Top Layer w0.2: D1.2 105.87,77.43 D2.1 109.07,76.7 106.875,76.7 Q1.3
NetD3_2: D3.2 R6.2 | length 2.2
  Top Layer w0.2: R6.2@75.65,96.8 75.7,96.85 D3.2
NetD3_4: D3.4 R7.2 | length 2.2
  Top Layer w0.2: R7.2@75.65,95.3 75.7,95.35 D3.4
NetD4_1: D4.1 Q1.1 R2.1 R8.2 R11.2 TP9.1 U1.1 U4.4 | length 43
  Top Layer w0.2: R8.2@92.75,74.1 91.7,73.05 91.7,69.78 U1.1 U4.4 93.02,65.1 TP9.1 97.5,65.1 100.9,68.5 100.9,70.35 101.2,70.65 D4.1 101.425,71.925 101.9,72.4 107.1,72.4 107.7,73 107.7,74.05 107.3,74.45 Q1.1
  Top Layer w0.5: R11.2@98.25,61.7 98.25,65.05 101.425,68.225 D4.1
NetJ4_2: J4.2 U5.14 | length 21.1
  Bottom Layer w0.2: J4.2@37.4,81.643 37.4,81.9 36.5,82.8 36.5,84.9 37.2,85.6 44.3,85.6 45.2,86.5 45.2,91.3 47.005,93.105 U5.14
NetJ4_3: J4.3 U5.13 | length 16.2
  Bottom Layer w0.2: J4.3@37.4,84.386 37.986,84.386 38.4,84.8 44.4,84.8 45.8,86.2 45.8,90.9 46.735,91.835 U5.13
NetJ8_1: J8.1 J8.2 R17.1 | length 14.6
  Top Layer w1: R17.1@99.025,95.1 102.725,91.4 104,91.4 ; J8.2 104,91.4 ; J8.1 104,91.4
NetJ8_3: J8.3 R16.1 | length 11.2
  Top Layer w1: R16.1@99.025,87.1 101.325,84.8 108.4,84.8 J8.3
NetJ9_4: J9.4 R18.1 | length 4.1
  Top Layer w0.2: J9.4@29.6,56.65 30.65,56.65 v1(31.3,57.3)
  Bottom Layer w0.2: v1(31.3,57.3) 31.3,57.8 31.7,58.2 R18.1@32.75,58.2
NetJ10_1: J10.1 U7.1 | length 2.4
  Bottom Layer w0.2: J10.1 46.35,64.3 U7.1
NetQ1_2: Q1.2 Q1.4 R2.2 | length 4.2
  Top Layer w0.2: Q1.4 104.55,75.75 105.2,75.1 Q1.2 107.05,75.1 R2.2@107.7,75.75
NetQ1_5: Q1.5 Q1.6 R1.1 | length 2.6
  Top Layer w0.2: R1.1@102.35,74 103.625,74 Q1.6 Q1.5
NetQ2_1: Q2.1 U3.1 | length 8.5
  Top Layer w0.2: U3.1 97.247,75.953 97.5,75.7 97.5,73.6 98.2,72.9 98.2,70.9 96.95,69.65 Q2.1
NetQ2_2: Q2.2 R10.1 | length 2.7
  Top Layer w0.2: R10.1@96.65,67.8 96.65,68.05 98.25,69.65 Q2.2
NetQ2_3: Q2.3 U1.2 | length 5.2
  Top Layer w0.2: U1.2 92.75,71.65 97.4,71.65 Q2.3
NetQ3_1: Q3.1 R13.2 | length 2.1
  Top Layer w0.2: R13.2@96.45,55.8 Q3.1
NetQ3_3: Q3.3 R11.1 | length 2.3
  Top Layer w0.5: R11.1@96.55,61.7 96.55,60.45 96.95,60.05 Q3.3
NetR12_1: R12.1 U4.1 | length 2.7
  Top Layer w0.2: R12.1@81,64.35 82.23,64.35 U4.1
NetR13_1: R13.1 R15.2 U4.3 | length 11.6
  Top Layer w0.2: U4.3 94.17,62.83 95.3,61.7 95.3,60.7 97.5,58.5 97.5,57 98.1,56.4 R13.1 R15.2
NetR19_2: R19.2 U7.46 | length 3.1
  Bottom Layer w0.2: R19.2@42.35,58.8 43.3,59.75 U7.46
NetR20_2: R20.2 U7.47 | length 2.7
  Bottom Layer w0.2: R20.2@42.35,60.3 42.4,60.25 U7.47
NetR22_2: R22.2 U7.3 | length 8.1
  Bottom Layer w0.2: R22.2@46.25,69.6 47.5,68.35 47.5,63.036 47.4,62.936 47.4,62.125 U7.3
PDI_CLK: J3.5@63.86,97.27 R14.2 U2.8 | length 18.5
  Top Layer w0.2: J3.5@63.86,97.27 65.1,96.03 65.1,93.3 65.5,92.9 67.2,92.9 U2.8
PDI_DATA: J3.1@68.94,97.27 U2.7 | length 16.8
  Top Layer w0.2: U2.7 68,90.4 67.7,90.7 67.7,96.03 J3.1@68.94,97.27
RESET: C16.1 J11.6 R21.1 U7.4 | length 40.8
  Top Layer w0.2: v1(47.2,60.4) 47.9,61.1 v1(59.3,61.1)
  Bottom Layer w0.2: v1(47.2,60.4) 47.85,61.05 U7.4 47.9,62.125 47.9,68.3 C16.1@49.15,69.55 ; C16.1 R21.1 ; v1(59.3,61.1) 64.6,61.1 65.3,60.4 65.3,55.3 64.6,54.6 62.4,54.6 61.9,54.1 J11.6
RS232_3V3: C7.1 C8.1 J6.1 TP12.1 U5.16 | length 37.1
  Top Layer w0.2: J6.1 TP12.1
  Top Layer w0.3: J6.1 42.9,68.25 42.9,86.7 44.9,88.7 v1(44.9,93.2)
  Bottom Layer w0.3: v1(44.9,93.2) 45.3,93.6 C7.1 C8.1 45.345,95.645 U5.16
RX_232: J1.2@51.47,81.24 TP4.1 U5.12 | length 15
  Bottom Layer w0.2: U5.12 50.035,90.565 50.5,90.1 50.5,82.21 51.47,81.24 51.53,81.3 TP4.1
RX_USB: J1.6@51.47,76.16 TP6.1 U7.24 | length 30
  Bottom Layer w0.2: J1.6@51.47,76.16 51.63,76 56.5,76 57.2,75.3 57.2,55.6 56.85,55.25 U7.24
RXD: J1.4@51.47,78.7 TP3.1 U2.14 | length 18.3
  Top Layer w0.2: J1.4@51.47,78.7 55.7,78.7 58.6,75.8 U2.14
  Bottom Layer w0.2: J1.4@51.47,78.7 TP3.1
SW1: SW1.3 SW1.4 U2.21 | length 50.5
  Top Layer w0.2: SW1.3 41.022,52.8 43.178,52.8 SW1.4 47.978,57.6 70,57.6 70.4,58 U2.21
SW2: SW2.3 SW2.4 U2.22 | length 39
  Top Layer w0.2: SW2.3 52.889,53.2 55.845,53.2 SW2.4 59.845,57.2 70.889,57.2 71.2,57.511 U2.22
SW3: SW3.3 SW3.4 U2.23 | length 26.6
  Top Layer w0.2: SW3.3 62.633,56.333 70.023,56.333 SW3.4 72,57.089 U2.23
SW4: SW4.3 SW4.4 U2.24 | length 26
  Top Layer w0.2: U2.24 72.8,57.822 SW4.3 SW4.4
TX_232: J1.1@48.93,81.24 TP2.1 U5.11 | length 13.3
  Bottom Layer w0.2: TP2.1 48.87,81.3 48.93,81.24 50,82.31 50,88.9 49.605,89.295 U5.11
TX_USB: J1.5@48.93,76.16 TP8.1 U7.23 | length 33.5
  Bottom Layer w0.2: TP8.1 46.16,76.16 48.93,76.16 50.19,74.9 56.3,74.9 56.8,74.4 56.8,56.1 56.45,55.75 U7.23
TXD: J1.3@48.93,78.7 TP5.1 U2.13 | length 21.6
  Top Layer w0.2: J1.3@48.93,78.7 50.08,79.85 55.45,79.85 58.7,76.6 U2.13
  Bottom Layer w0.2: TP5.1 J1.3@48.93,78.7
USB_3V3: C19.1 C20.1 C21.1 C22.1 C23.1 C24.1 J7.1 J11.4 R18.2 R21.2 TP13.1 U7.8 U7.18 U7.19 U7.27 U7.31 U7.40 U7.45 | length 100.8
  Top Layer w0.2: J7.1 42.05,62.1 45.4,62.1 TP13.1
  Top Layer w0.3: v1(38.6,58.2) 38.9,58.5 41.55,58.5 ; J7.1 41.55,58.5 ; v1(42.3,53.6) 41.55,54.35 41.55,58.5 ; v1(55.2,54.1) 55.2,56.5 v1(55.2,56.4)
  Bottom Layer w0.2: 49.4,50.9 49.8,50.5 60.2,50.5 60.63,50.93 J11.4 ; R21.2@50.85,71.2 53.8,71.2 54.3,70.7 54.3,65.1 C20.1@53.6,64.4
  Bottom Layer w0.3: R18.2@34.4,58.2 v1(38.6,58.2) ; U7.40 C22.1@42.35,56.75 ; U7.45 43.95,59.25 43.4,58.7 43.4,57.8 C22.1@42.35,56.75 ; U7.8 49.85,62.957 50.293,63.4 51.4,63.4 51.8,63.8 C23.1 C20.1 53.6,64.4 56,64.4 56.35,64.05 56.35,58.55 55.8,58 C24.1 C24.1@55.2,57.9 ; U7.27 50.85,54.807 50.557,55.1 49.1,55.1 48.85,54.85 U7.31 48.85,51.95 C21.1 ; U7.19 C24.1@55.2,57.75 ; U7.18 54.85,58.25 C24.1@55.2,57.9 ; v1(55.2,54.1) 55.2,51.5 54.6,50.9 49.4,50.9 C21.1 ; v1(55.2,56.4) C24.1@55.2,57.75 ; C22.1@42.35,56.75 C22.1 v1(42.3,53.6) 44.2,51.7 C21.1 ; C24.1@55.2,57.75 C24.1@55.2,57.9
USB_DM: D5.1 J9.2 R19.1 | length 15.1
  Top Layer w0.2: J9.2@29.6,55.35 31.05,55.35 v1(31.3,55.1)
  Bottom Layer w0.2: v1(31.3,55.1) 31.5,55.3 39.2,55.3 39.7,55.8 39.7,58.3 40.2,58.8 R19.1@40.65,58.8 ; D5.1 32.7,55.3
USB_DP: D6.1 J9.3 R20.1 | length 16.2
  Top Layer w0.2: J9.3@29.6,56 v1(31.3,56)
  Bottom Layer w0.2: v1(31.3,56) 31.6,55.7 32.7,55.7 ; D6.1 32.7,55.7 ; R20.1@40.65,60.3 39.6,60.3 39.3,60 39.3,56.2 38.8,55.7 32.7,55.7
VBUS: C10.1 J9.1 U6.2 | length 20.9
  Top Layer w0.3: J9.1 30.6,54.7 31.4,53.9 32.1,53.9
  Top Layer w0.5: 32.1,53.9 33,54.8 33,59.4 31.6,60.8 30.4,60.8 28.9,62.3 28.9,65.075 32.575,65.075 U6.2@33,65.5
VCC_3V3: C11.1 J5.2 J6.2 J7.2 TP10.1 U6.3 | length 16.4
  Top Layer w0.2: C11.1@37,65.075 37.6,64.475 TP10.1
  Top Layer w0.5: U6.3 36.3,62.6 37,63.3 37,65.075 39.775,65.075 ; J7.2 39.85,64.3 J6.2
VDDCORE: C17.1 C18.1 U7.5 U7.7 | length 6.2
  Bottom Layer w0.3: U7.5 48.35,63.95 C17.1 49.902,64.4 49.902,63.802 49.35,63.25 U7.7
pads on no net: J1.1@48.93,81.24 J1.2@51.47,81.24 J1.3@48.93,78.7 J1.4@51.47,78.7 J1.5@48.93,76.16 J1.6@51.47,76.16 J3.1@68.94,97.27 J3.2@68.94,94.73 J3.3 J3.4 J3.5@63.86,97.27 J3.6@63.86,94.73 J4.1 J4.4 J4.6 J4.7 J4.8 J4.9 J11.7 J11.8 U2.2 U2.3 U2.4 U2.9 U2.10 U2.11 U2.12 U2.15 U2.16 U2.19 U2.20 U2.27 U2.28 U2.29 U2.30 U2.31 U5.7 U5.8 U5.9 U5.10 U7.11 U7.12 U7.13 U7.14 U7.15 U7.16 U7.20 U7.21 U7.22 U7.32 U7.33 U7.34 U7.35 U7.36 U7.37 U7.38 U7.39 U7.41 U7.42

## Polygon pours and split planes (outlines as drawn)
GND on Bottom Layer "GND_BOTTOM" (solid, remove dead copper, pour order 6): 25,100 25,50 84.5,50 84.5,100
GND_DALI on Bottom Layer "GND_DALI_BOTTOM" (solid, remove dead copper, pour order 8): 91.2,50 100.1,50 100.1,58.9 101.6,60.4 105,60.4 105.9,61.3 105.9,69.3 109.1,72.5 110.9,72.5 111.3,72.9 111.3,80 110.9,80.4 91.9,80.4 91.2,79.7
GND on Top Layer "GND_TOP" (solid, remove dead copper, pour order 5): 25,100 25,50 84.5,50 84.5,100
GND_DALI on Top Layer "GND_DALI_TOP" (solid, remove dead copper, pour order 7): 91.2,50 100.1,50 100.1,58.9 101.6,60.4 105,60.4 105.9,61.3 105.9,69.3 109.1,72.5 110.9,72.5 111.3,72.9 111.3,80 110.9,80.4 91.9,80.4 91.2,79.7

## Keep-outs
Keep-Out Layer:
  lines w0.15: 25,54.1 26.9,54.1 ; 25,57.9 26.9,57.9 ccw(c26.9,58.35) 26.9,58.8 ; 26.9,53.197 ccw(c26.9,53.647) 26.9,54.097
  lines w0.2: 25,54.1 25,57.9 ; 26.9,53.2 25,53.2 25,50 27,50 115,50 115,100 25,100 25,58.8 26.9,58.8

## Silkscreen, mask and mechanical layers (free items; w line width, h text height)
Top Overlay:
  lines w0.2: 92.05,78.325 87.3,80.8 ; 111,78.6 102.9,82.5 ; 87.3,80.8 87.3,85 87.5,85 95.3,85 95.3,83.8 97.6,83.8 97.6,82.5 102.9,82.5 ; 87.3,80.8 102.9,80.8 102.9,82.5
  text "1" at 70.8,96.9 h1
  text "B" at 42.4,94.3 h10
  text "PDI" at 62.4,91.7 h2
  text "DALI Master based on XmegaE5" at 49,88.3 h3
  text "RS232" at 41.9,87.4 h2
  text "DC 16V" at 106.2,82.8 h2
  text "1" at 46.4,80.8 h1
  text "2" at 53.5,80.8 h1
  text "3" at 46.2,78.2 h1
  text "4" at 53.4,78.1 h1
  text "5" at 46.1,75.7 h1
  text "6" at 53.5,75.7 h1
  text "TX" at 47.6,73.3 h2
  text "RX" at 50.6,73.3 h2
  text "A08-1927 Rev 2" at 64.3,64 h1.5
  text "DALI" at 110.7,63.4 h2
  text "Atmel Corp © 2013" at 64.3,61.5 h1.5
  text "USB" at 25.6,61.3 h2
Bottom Overlay:
  lines w0.2: 40.5,69.4 42.6,69.4 43.7,69.4 43.7,75 40.5,75 40.5,69.4 ; 55.1,63.8 60.8,63.8 60.8,67.3 55.1,67.3 55.1,64 55.1,63.8
Mechanical 1:
  lines w0.2: 26.9,53.194 ccw(c26.9,53.647) 26.9,54.1 25,54.1 25,57.9 26.9,57.9 ccw(c26.9,58.35) 26.9,58.8 25,58.8 25,100 115,100 115,50 27.2,50 25,50 25,53.2 26.9,53.2

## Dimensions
25,50 to 115,50 on Mechanical 1
115,100 to 115,50 on Mechanical 1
